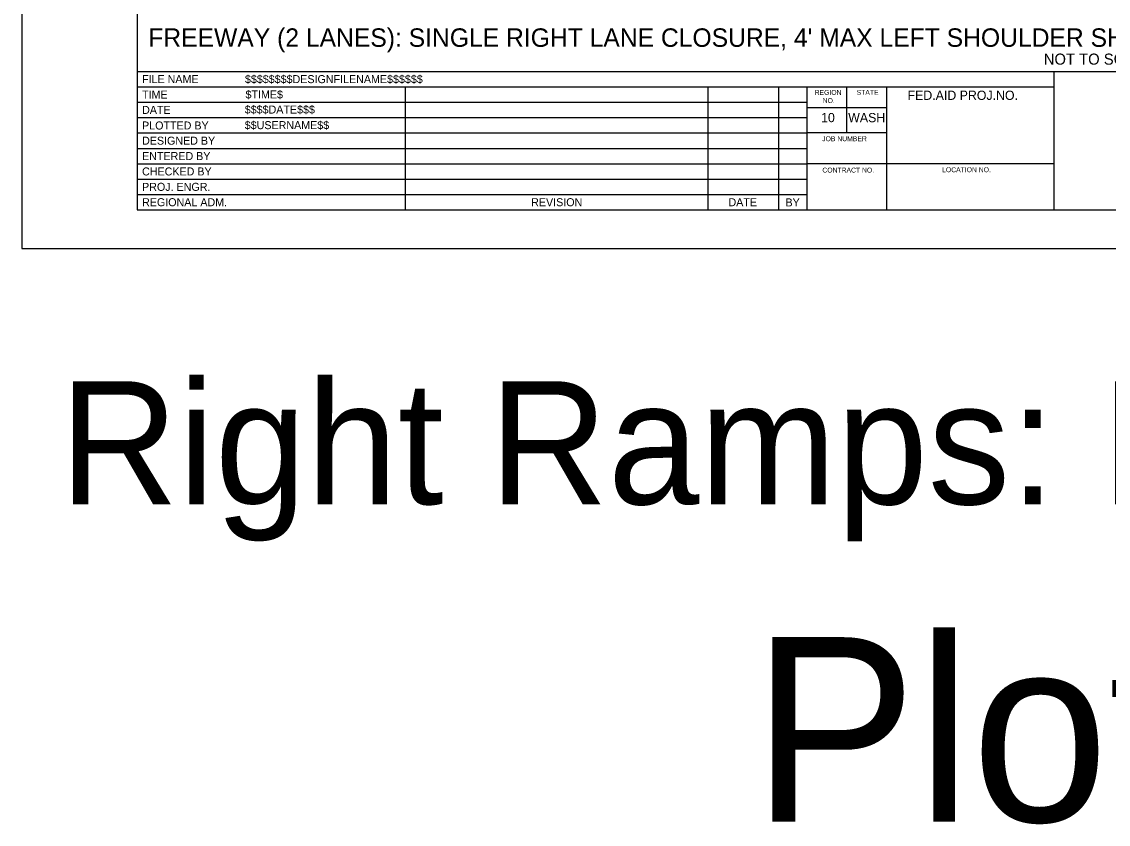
# Model space of a CAD drawing. Extents: x 99999 to 100116, y 99995 to 100013.
# Drawn here: x 100039.06 to 100047.9, y 99995.01 to 100001.53 of the extents above; entities that cross this region are included whole.
import ezdxf

# ---------------------------------------------------------------- set-up
doc = ezdxf.new("R2010")
doc.units = 0
for name, color, linetype in [('SH_DE_DetailHeading1Text', 7, 'Continuous'), ('SH_GI_PlotLimits', 7, 'Continuous'), ('SH_GI_SheetBorder', 7, 'Continuous'), ('SH_GI_SheetLocationText', 7, 'Continuous'), ('SH_GI_SheetTextInCells', 7, 'Continuous'), ('SH_GI_TitleBlockText', 7, 'Continuous')]:
    doc.layers.add(name, color=color, linetype=linetype)

msp = doc.modelspace()

# ---------------------------------------------------------------- linework, layer by layer
at = {"layer": 'SH_GI_PlotLimits'}
msp.add_lwpolyline([(100039.0625, 99999.6875), (100056.0625, 99999.6875), (100056.0625, 100010.6875), (100039.0625, 100010.6875)], close=True, dxfattribs=at)
at = {"layer": 'SH_GI_SheetBorder'}
for p, q in [((100040, 100010.375), (100040, 100000)), ((100040, 100001.1259), (100055.75, 100001.1259)), ((100047.4566, 100000), (100047.4566, 100001.1259)), ((100040, 100001.0008), (100047.4566, 100001.0008)), ((100042.179, 100001.0008), (100042.179, 100000)), ((100044.641, 100001.0008), (100044.641, 100000)), ((100045.2164, 100001.0008), (100045.2164, 100000)), ((100045.4451, 100001.0008), (100045.4451, 100000)), ((100045.7719, 100000.6255), (100045.7719, 100001.0008)), ((100046.0956, 100000), (100046.0956, 100001.0008)), ((100040, 100000.8757), (100042.1821, 100000.8757)), ((100042.1821, 100000.8757), (100045.4466, 100000.8757)), ((100040, 100000.7506), (100042.1821, 100000.7506)), ((100042.1821, 100000.7506), (100045.4466, 100000.7506)), ((100046.0958, 100000.831), (100045.4466, 100000.831)), ((100040, 100000.6255), (100045.4466, 100000.6255)), ((100046.0958, 100000.6255), (100045.4466, 100000.6255)), ((100040, 100000.5004), (100045.4466, 100000.5004)), ((100040, 100000.3753), (100045.4466, 100000.3753)), ((100047.4566, 100000.3753), (100045.4466, 100000.3753)), ((100040, 100000.2502), (100045.4466, 100000.2502)), ((100040, 100000.1251), (100045.4466, 100000.1251)), ((100040, 100000), (100055.75, 100000))]:
    msp.add_line(p, q, dxfattribs=at)

# ---------------------------------------------------------------- texts
at = {"layer": 'SH_DE_DetailHeading1Text'}
for s, height, p in [("FREEWAY (2 LANES): SINGLE RIGHT LANE CLOSURE, 4' MAX LEFT SHOULDER SHIFT (55 MPH WORK ZONE SPEED LIMIT, 40 MPH ADVISORY SPEED)", 0.15, (100040.0913, 100001.3259)), ('NOT TO SCALE', 0.09, (100047.3727, 100001.1809))]:
    msp.add_text(s, height=height, rotation=360, dxfattribs=at).set_placement(p)
at = {"layer": 'SH_GI_SheetLocationText'}
for s, height, p in [('Right Ramps: Parallel On-Ramp', 1, (100039.3704, 99997.6071)), ('Plot 3', 1.5, (100045.0008, 99995.0267))]:
    msp.add_text(s, height=height, dxfattribs=at).set_placement(p)
at = {"layer": 'SH_GI_SheetTextInCells'}
for s, height, p in [('FILE NAME', 0.06505, (100040.041, 100001.0308)), ('TIME', 0.06505, (100040.041, 100000.9057)), ('REGION', 0.04003, (100045.5099, 100000.9352)), ('STATE', 0.04003, (100045.8511, 100000.9357)), ('FED.AID PROJ.NO.', 0.07506, (100046.2652, 100000.8945)), ('DATE', 0.06505, (100040.041, 100000.7806)), ('NO.', 0.04003, (100045.5752, 100000.869)), ('10', 0.07506, (100045.5621, 100000.7131)), ('WASH', 0.07506, (100045.7826, 100000.7131)), ('PLOTTED BY', 0.06505, (100040.041, 100000.6538)), ('DESIGNED BY', 0.065052, (100040.041, 100000.5304)), ('JOB NUMBER', 0.04003, (100045.5712, 100000.5587)), ('ENTERED BY', 0.06505, (100040.041, 100000.4053)), ('CHECKED BY', 0.06505, (100040.041, 100000.2802)), ('CONTRACT NO.', 0.040032, (100045.5725, 100000.3037)), ('LOCATION NO.', 0.040032, (100046.5465, 100000.3067)), ('PROJ. ENGR.', 0.065052, (100040.041, 100000.1551)), ('REGIONAL ADM.', 0.065052, (100040.041, 100000.03)), ('REVISION', 0.06505, (100043.2048, 100000.03)), ('DATE', 0.06505, (100044.8091, 100000.03)), ('BY', 0.06505, (100045.2725, 100000.0285))]:
    msp.add_text(s, height=height, dxfattribs=at).set_placement(p)
at = {"layer": 'SH_GI_TitleBlockText'}
for s, height, p in [('$$$$$$$$DESIGNFILENAME$$$$$$', 0.065052, (100040.8775, 100001.0308)), ('$TIME$', 0.06505, (100040.882, 100000.9059)), ('$$$$DATE$$$', 0.065052, (100040.8759, 100000.7835)), ('$$USERNAME$$', 0.065052, (100040.8759, 100000.6567))]:
    msp.add_text(s, height=height, dxfattribs=at).set_placement(p)

doc.saveas('drawing.dxf')
